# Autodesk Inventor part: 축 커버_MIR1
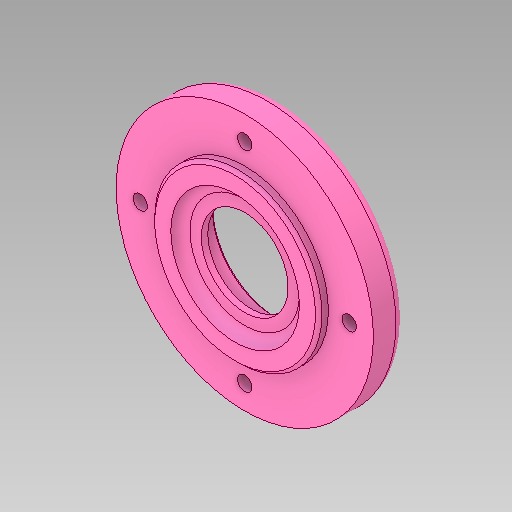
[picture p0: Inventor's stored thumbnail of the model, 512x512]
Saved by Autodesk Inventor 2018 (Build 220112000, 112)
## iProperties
Created: 2015-10
Part Number: 축 커버_MIR1
Material: 강철, 연강
Document SubType Name: Modeling
Designer: home
Density: 7.86 g/cm^3
Appearance: 강철
Author: mdu
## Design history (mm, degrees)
derived "축 커버.ipt"
  sketch "스케치1"
    geometry: C1 r 40 at (0, 0) reference; C2 r 26 at (0, 0) reference; 1 further point
    dimensions: "d0" = 10 dimension on point (0, 0) C1.centre C1 C2.centre C2
  sketch "스케치2"
    geometry: C1 r 20 at (0, 0) reference; 1 further point
    dimensions: "d0" = 10 dimension on point (0, 0) C1.centre C1
  sketch "스케치3"
    geometry: C1 r 1.621 at (0, 32.5) reference; 1 further point
    dimensions: "d0" = 10 dimension on point (0, 0) C1.centre C1
feature "솔리드1::축 커버.ipt"
tag "피쳐 태그1"
node "솔리드1"
